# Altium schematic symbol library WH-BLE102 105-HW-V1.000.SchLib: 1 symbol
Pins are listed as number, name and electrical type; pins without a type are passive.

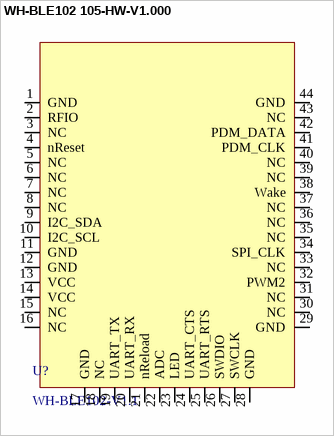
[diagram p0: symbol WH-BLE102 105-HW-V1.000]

## WH-BLE102 105-HW-V1.000
designator U?, comment WH-BLE102-V1.1
pins: 1 GND, 2 RFIO, 3 NC, 4 nReset, 5 NC, 6 NC, 7 NC, 8 NC, 9 I2C_SDA, 10 I2C_SCL, 11 GND, 12 GND, 13 VCC, 14 VCC, 15 NC, 16 NC, 17 GND, 18 NC, 19 UART_TX, 20 UART_RX, 21 nReload, 22 ADC, 23 LED, 24 UART_CTS, 25 UART_RTS, 26 SWDIO, 27 SWCLK, 28 GND, 29 GND, 30 NC, 31 NC, 32 PWM2, 33 NC, 34 SPI_CLK, 35 NC, 36 NC, 37 NC, 38 Wake, 39 NC, 40 NC, 41 PDM_CLK, 42 PDM_DATA, 43 NC, 44 GND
